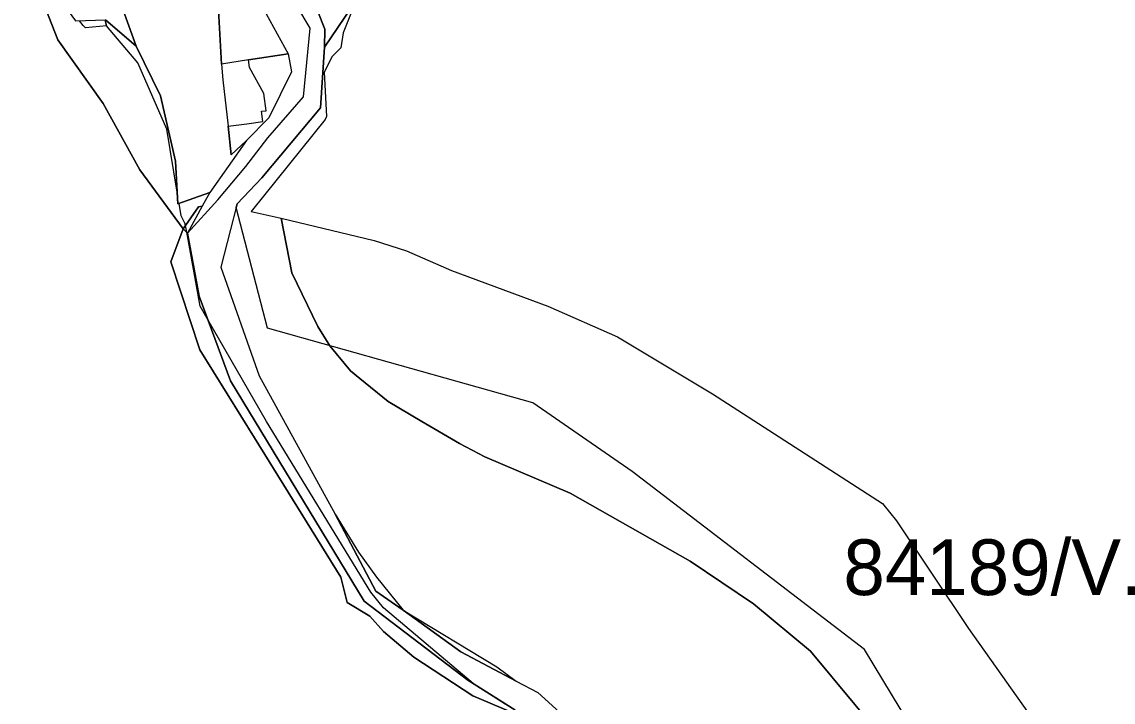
# Model space of a CAD drawing. Extents: x -477304 to -465429, y -1159113 to -1149210.
# Drawn here: x -473381.9 to -473088.1, y -1152924.3 to -1152741 of the extents above; entities that cross this region are included whole.
import ezdxf

# ---------------------------------------------------------------- set-up
doc = ezdxf.new("R2010")
doc.units = 0
for name, color, linetype in [('BPEJ_s', 7, 'Continuous'), ('PUPFL_s', 7, 'Continuous'), ('trav_porost_s', 7, 'Continuous'), ('voda_s', 7, 'Continuous')]:
    doc.layers.add(name, color=color, linetype=linetype)

msp = doc.modelspace()

# ---------------------------------------------------------------- linework, layer by layer
at = {"layer": 'BPEJ_s'}
for points in [[(-473359.45, -1152740.48), (-473359.28, -1152741.36), (-473359.13, -1152742.11), (-473364.73, -1152742.69), (-473365.37, -1152742.05), (-473366.35, -1152740.77)], [(-473251.75, -1152924.83), (-473260.05, -1152919.51), (-473260.38, -1152919.23), (-473284.52, -1152898.87), (-473287.92, -1152894.62), (-473316.01, -1152848.66), (-473331.97, -1152820.92), (-473333.88, -1152817.59), (-473337.51, -1152797.71), (-473337.85, -1152795.88), (-473337.89, -1152795.66), (-473337.92, -1152795.46), (-473338.99, -1152793.33), (-473339.54, -1152789.98), (-473339.87, -1152790.1), (-473340.04, -1152786.89), (-473342.82, -1152769.93), (-473350.69, -1152752.05), (-473359.13, -1152742.11), (-473364.73, -1152742.69), (-473365.37, -1152742.05), (-473366.35, -1152740.77)], [(-473337.92, -1152795.46), (-473338.99, -1152793.33), (-473339.54, -1152789.98), (-473339.87, -1152790.1), (-473340.04, -1152786.89), (-473342.82, -1152769.93), (-473350.69, -1152752.05), (-473359.13, -1152742.11), (-473359.28, -1152741.36), (-473359.45, -1152740.48)], [(-473293.24, -1152738.65), (-473295.37, -1152743.97), (-473296.01, -1152748.01), (-473298.35, -1152750.35), (-473300.48, -1152754.61), (-473299.84, -1152766.52), (-473300.26, -1152767.37), (-473309.84, -1152779.29), (-473320.12, -1152792.09), (-473312.11, -1152793.88), (-473287.07, -1152799.93), (-473278.34, -1152802.7), (-473266.22, -1152808.01), (-473240.26, -1152817.59), (-473221.53, -1152825.89), (-473196, -1152841.21), (-473150.25, -1152870.78), (-473146.42, -1152875.47), (-473127.06, -1152904.4), (-473106.63, -1152933.34)], [(-473293.24, -1152738.65), (-473295.37, -1152743.97), (-473296.01, -1152748.01), (-473298.35, -1152750.35), (-473300.48, -1152754.61), (-473299.84, -1152766.52), (-473300.26, -1152767.37)], [(-473300.26, -1152767.37), (-473309.84, -1152779.29), (-473320.12, -1152792.09), (-473312.11, -1152793.88), (-473309.2, -1152808.65), (-473302.18, -1152823.12), (-473298.96, -1152828.26), (-473293.45, -1152835.04), (-473290.93, -1152837.09), (-473283.24, -1152843.34), (-473274.18, -1152848.67), (-473264.09, -1152854.61), (-473257.28, -1152858.23), (-473234.3, -1152868.02), (-473201.96, -1152886.32), (-473184.93, -1152897.81), (-473169.61, -1152910.57), (-473145.78, -1152939.3)], [(-473145.78, -1152939.3), (-473169.61, -1152910.57), (-473184.93, -1152897.81), (-473201.96, -1152886.32), (-473234.3, -1152868.02), (-473257.28, -1152858.23), (-473264.09, -1152854.61), (-473274.18, -1152848.67), (-473283.24, -1152843.34), (-473290.93, -1152837.09), (-473293.45, -1152835.04), (-473298.96, -1152828.26), (-473302.18, -1152823.12), (-473309.2, -1152808.65), (-473312.11, -1152793.88), (-473287.07, -1152799.93), (-473278.34, -1152802.7), (-473266.22, -1152808.01), (-473240.26, -1152817.59), (-473221.53, -1152825.89), (-473196, -1152841.21), (-473150.25, -1152870.78), (-473146.42, -1152875.47), (-473127.06, -1152904.4), (-473106.63, -1152933.34)], [(-473251.75, -1152924.83), (-473260.05, -1152919.51), (-473260.38, -1152919.23), (-473284.52, -1152898.87), (-473287.92, -1152894.62), (-473316.01, -1152848.66), (-473331.97, -1152820.92), (-473333.88, -1152817.59), (-473337.51, -1152797.71), (-473337.85, -1152795.88), (-473337.89, -1152795.66), (-473337.92, -1152795.46)]]:
    msp.add_lwpolyline(points, dxfattribs=at)
at = {"layer": 'PUPFL_s'}
for points in [[(-473300.42, -1152747.86), (-473300.33, -1152743.04), (-473308.36, -1152722.56), (-473286.02, -1152708.39), (-473284.2, -1152723.81)], [(-473381.88, -1152721.04), (-473367.39, -1152740.81), (-473359.38, -1152740.48), (-473351.13, -1152747.56), (-473344.52, -1152760.98), (-473340.49, -1152778.59), (-473339.87, -1152790.1), (-473331.3, -1152787.03), (-473333.33, -1152790.73), (-473334.29, -1152790.85), (-473338.48, -1152796.77), (-473350.09, -1152780.92), (-473360.01, -1152763.05), (-473372.17, -1152745.88)]]:
    msp.add_lwpolyline(points, close=True, dxfattribs=at)
for points in [[(-473381.88, -1152721.04), (-473372.17, -1152745.88), (-473360.01, -1152763.05), (-473350.09, -1152780.92), (-473338.48, -1152796.77), (-473341.8, -1152805.68), (-473333.96, -1152829.42), (-473319.24, -1152853.07), (-473296.04, -1152890.62), (-473294.31, -1152897.45), (-473288.25, -1152901.13), (-473284.52, -1152905.27), (-473276.37, -1152912.11), (-473260.46, -1152922.55), (-473250.52, -1152926.81)], [(-472788.53, -1152855.25), (-472815.37, -1152871.31), (-472838.15, -1152891.01), (-472862.34, -1152914.65), (-472881.39, -1152932.72), (-472907.31, -1152967.06), (-472928.03, -1152969.19), (-472962.85, -1152969.01), (-473001.34, -1152978.85), (-473028.57, -1152989.07), (-473051.84, -1152985.25), (-473081.12, -1152990.24), (-473106.29, -1152990.89), (-473155.08, -1152910.13), (-473217.56, -1152862.11), (-473244.36, -1152843.64), (-473315.8, -1152823.53), (-473324.18, -1152791.02), (-473323.92, -1152790.07), (-473317.27, -1152783.1), (-473301.51, -1152764.2), (-473300.42, -1152747.86), (-473284.2, -1152723.81)]]:
    msp.add_lwpolyline(points, dxfattribs=at)
at = {"layer": 'trav_porost_s'}
for points in [[(-473356.62, -1152732.34), (-473351.13, -1152747.56), (-473359.38, -1152740.48)], [(-473318.05, -1152735.26), (-473310.15, -1152749.67), (-473320.85, -1152751.31), (-473328.11, -1152752.43), (-473328.96, -1152737.93)]]:
    msp.add_lwpolyline(points, dxfattribs=at)
for points in [[(-473340.49, -1152778.59), (-473344.52, -1152760.98), (-473351.13, -1152747.56), (-473356.62, -1152732.34), (-473347.05, -1152732.79), (-473328.96, -1152737.93), (-473328.11, -1152752.43), (-473327.78, -1152756.7), (-473326.38, -1152769.14), (-473325.5, -1152776.9), (-473321.43, -1152772.99), (-473331.3, -1152787.03), (-473339.87, -1152790.1)], [(-473317.34, -1152765.14), (-473316.13, -1152764.98), (-473316.72, -1152760.37), (-473320.62, -1152753.33), (-473320.85, -1152751.31), (-473310.15, -1152749.67), (-473309.31, -1152754.48), (-473315.43, -1152766.92), (-473321.43, -1152772.99), (-473325.5, -1152776.9), (-473326.38, -1152769.14), (-473321.29, -1152768.52), (-473316.98, -1152767.91)]]:
    msp.add_lwpolyline(points, close=True, dxfattribs=at)
at = {"layer": 'voda_s'}
for points in [[(-473308.36, -1152722.56), (-473300.33, -1152743.04), (-473300.42, -1152747.86), (-473301.51, -1152764.2), (-473317.27, -1152783.1), (-473323.92, -1152790.07), (-473324.18, -1152791.02), (-473325.7, -1152796.96), (-473328.29, -1152807.09), (-473318, -1152836.41), (-473297.51, -1152873.65), (-473286.59, -1152894.36), (-473279.2, -1152899.45)], [(-473249.22, -1152926.34), (-473261.81, -1152918.32), (-473289.72, -1152897.07), (-473325.73, -1152837.76), (-473334.17, -1152814.97), (-473337.29, -1152797.93), (-473329.13, -1152789.02), (-473321.55, -1152780.04), (-473315.65, -1152772.24), (-473306.07, -1152761.24), (-473304.28, -1152742.75), (-473314.8, -1152725.09)], [(-473279.2, -1152899.45), (-473263.69, -1152910.74), (-473248.82, -1152918.63), (-473243.01, -1152921.71), (-473235.18, -1152928.77)]]:
    msp.add_lwpolyline(points, dxfattribs=at)
for points in [[(-473334.29, -1152790.85), (-473333.33, -1152790.73), (-473337.29, -1152797.93), (-473338.48, -1152796.77)], [(-473260.46, -1152922.55), (-473276.37, -1152912.11), (-473284.52, -1152905.27), (-473288.25, -1152901.13), (-473294.31, -1152897.45), (-473296.04, -1152890.62), (-473319.24, -1152853.07), (-473333.96, -1152829.42), (-473341.8, -1152805.68), (-473338.48, -1152796.77), (-473337.29, -1152797.93), (-473334.17, -1152814.97), (-473325.73, -1152837.76), (-473289.72, -1152897.07), (-473261.81, -1152918.32), (-473249.22, -1152926.34), (-473219.97, -1152949.27), (-473222.65, -1152950.83), (-473225.72, -1152947.78), (-473230.71, -1152942.82), (-473234.06, -1152939.49), (-473250.52, -1152926.81)], [(-473286.45, -1152890.59), (-473279.2, -1152899.45), (-473286.59, -1152894.36), (-473297.51, -1152873.65), (-473291.24, -1152883.84)], [(-473279.2, -1152899.45), (-473254.05, -1152914.74), (-473248.82, -1152918.63), (-473263.69, -1152910.74)]]:
    msp.add_lwpolyline(points, close=True, dxfattribs=at)

# ---------------------------------------------------------------- texts
at = {"layer": 'BPEJ_s'}
msp.add_text('84189/V.', height=15, dxfattribs=at).set_placement((-473160.76, -1152895.43))

doc.saveas('drawing.dxf')
